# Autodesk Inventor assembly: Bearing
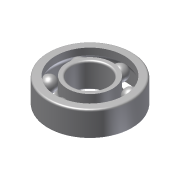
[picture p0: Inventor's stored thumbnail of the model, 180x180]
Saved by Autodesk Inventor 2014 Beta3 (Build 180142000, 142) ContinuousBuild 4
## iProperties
Created: 2011-01
Part Number: Bearing
Document SubType Name: Assembly
Designer: Beta-8540w
ClientObjectVersion: 1
Author: Beta-8540w
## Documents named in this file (2)
- C:\Inventor 2014 Essentials\Assemblies\Chapter 09\Design Accelerators\Bearing c0902.iam
- C:\Inventor 2014 Essentials\Content Center Files\en-US\SKF B - angular contact\SKF B7204 BE.ipt
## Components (1 placed, 1 different names)
1. SKF B- Angular contact SKF B7204 BE:1
